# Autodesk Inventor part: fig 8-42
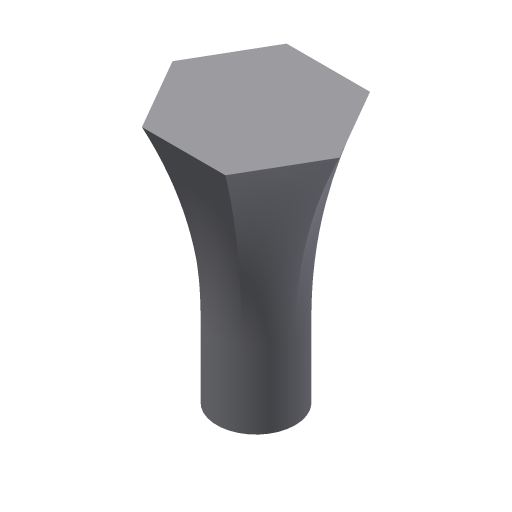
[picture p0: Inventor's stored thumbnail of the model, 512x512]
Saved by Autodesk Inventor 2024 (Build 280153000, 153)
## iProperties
Created: 2004-05
Part Number: fig 8-42
Document SubType Name: Modeling
Designer: CADCIM Technologies
Manufacturer: Standard
Standards Organization: Custom
Density: 1 g/cm^3
Material: Generic
Appearance: Default
Author: CADCIM Technologies
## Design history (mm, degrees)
sketch "Sketch1"
  geometry: C1 r 16.344 at (0, 0)
  constraints: 1 centre point
extrude "Extrusion1" new body sketch "Sketch1" distance "d0" = 30.75; taper "d1" = 0 deg
workplane "Work Plane1"
sketch "Sketch2"
  geometry: L1 (34.788, 0)-(17.394, -30.128); L2 (17.394, -30.128)-(-17.394, -30.128); L3 (-17.394, -30.128)-(-34.788, 0); L4 (-34.788, 0)-(-17.394, 30.128); L5 (-17.394, 30.128)-(17.394, 30.128); L6 (17.394, 30.128)-(34.788, 0); 2 further points
  constraints: 12 end point, 1 coincident, 12 other
loft "Loft2" sketch "Sketch2" dims "d8" = 90 deg, "d11" = 10, "d12" = 0, "d13" = 90 deg
  node "Edges2"
body "Solid1"
other parameters: "d2" = 75
